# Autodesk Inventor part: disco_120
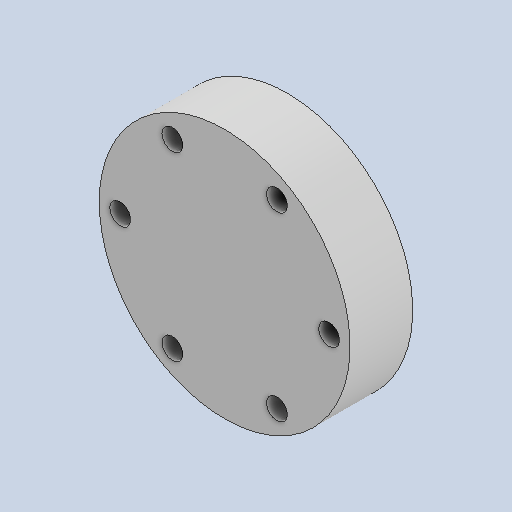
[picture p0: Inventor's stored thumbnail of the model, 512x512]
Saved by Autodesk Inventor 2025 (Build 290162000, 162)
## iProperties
Created: 2025-11
Part Number: disco_120
Material: Generico
Document SubType Name: Modeling
Designer: Ryzen5700u
Density: 1 g/cm^3
Appearance: Default
Author: Ryzen5700u
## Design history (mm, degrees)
feature "Solido1"
node "Solido2"
